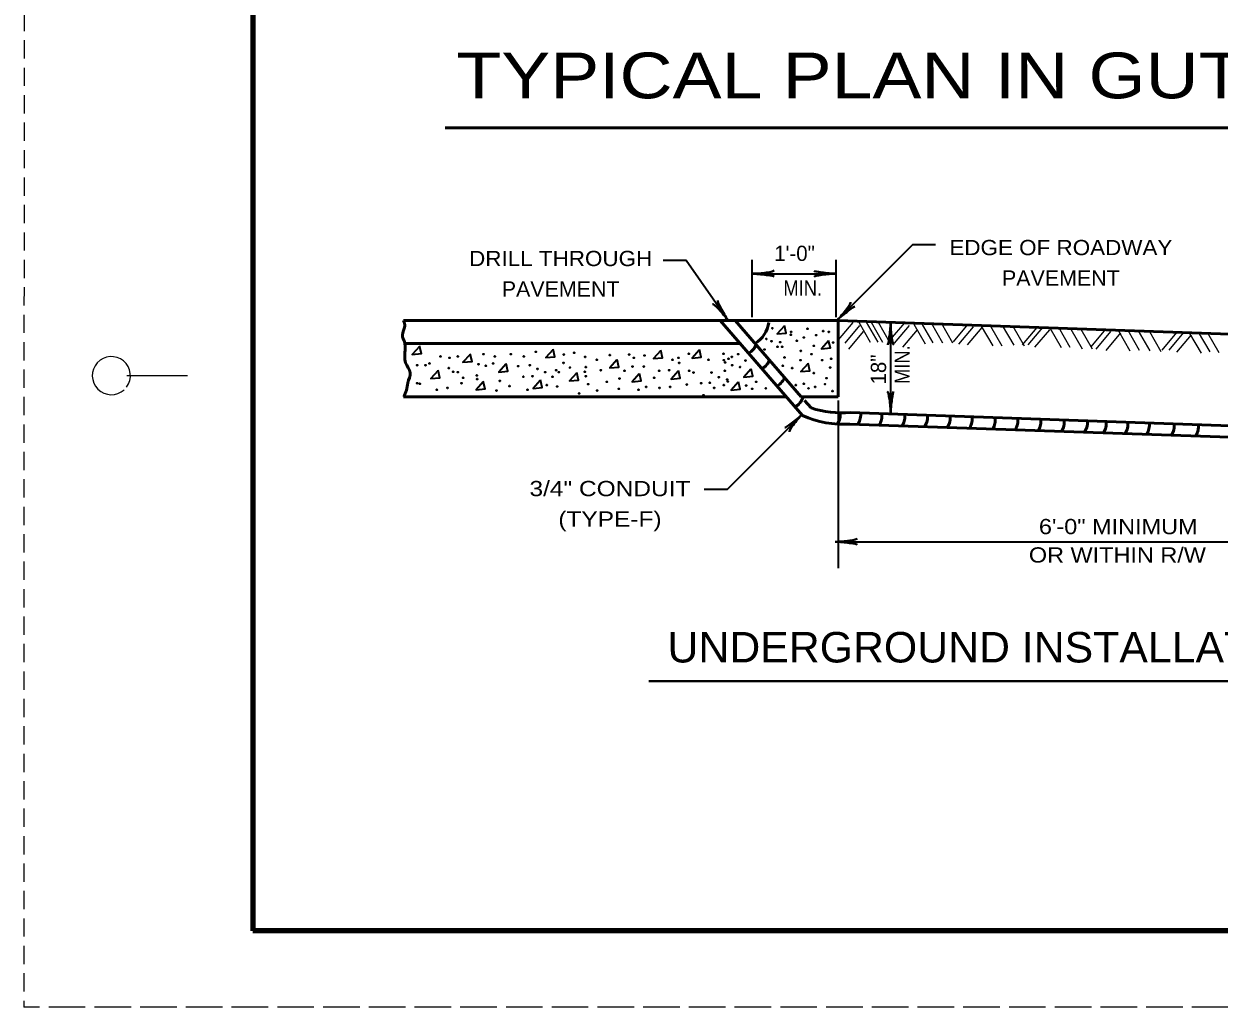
# Model space of a CAD drawing. Extents: x -58 to 622, y -372 to 68.
# Drawn here: x -58.5 to 98.3, y -372 to -243.1 of the extents above; entities that cross this region are included whole.
import ezdxf
from ezdxf.enums import TextEntityAlignment as Align

# ---------------------------------------------------------------- set-up
doc = ezdxf.new("R2010")
doc.units = 0
doc.header["$LTSCALE"] = 0.8
doc.linetypes.add('LONG_DASHED', pattern=[7.5, 6, -1.5])
doc.linetypes.add('MEDIUM_DASHED', pattern=[4.5, 3, -1.5])
doc.layers.add('1', color=7, linetype='Continuous', lineweight=35)
doc.layers.add('61', color=7, linetype='Continuous', lineweight=35)

msp = doc.modelspace()

# ---------------------------------------------------------------- linework, layer by layer
at = {"layer": '1', "linetype": 'MEDIUM_DASHED', "lineweight": 13}
msp.add_line((-58.4297, 67.9933), (-58.4898, -372.0467), dxfattribs=at)
at = {"layer": '1', "lineweight": 53}
for p, q in [((-3.2295, -256.7077), (194.5145, -256.7077)), ((32.8492, -281.9895), (43.6675, -294.4345)), ((34.8368, -281.9895), (43.5093, -291.966)), ((48.3367, -281.9895), (123.3002, -284.6073)), ((-8.6632, -284.9895), (35.4571, -284.9895)), ((41.4103, -291.9895), (-8.6632, -291.9895)), ((48.3367, -291.9895), (43.5063, -291.9895)), ((43.9508, -292.4741), (44.7996, -293.4504)), ((49.9544, -294.0532), (122.8722, -296.5997)), ((49.9021, -295.5523), (122.8199, -298.0987))]:
    msp.add_line(p, q, dxfattribs=at)
at = {"layer": '1'}
for p, q in [((37.076, -281.52), (37.076, -274.02)), ((48.076, -281.5199), (48.076, -274.0199)), ((37.076, -275.8309), (48.076, -275.8309)), ((55.2352, -282.3041), (55.2352, -294.1794)), ((48.3342, -292.4785), (48.3342, -314.4785)), ((47.9859, -310.9966), (123.3332, -310.9966))]:
    msp.add_line(p, q, dxfattribs=at)
at = {"layer": '1', "lineweight": 25}
for p, q in [((50.2675, -282.2197), (48.3392, -284.518)), ((51.0682, -282.2067), (52.5682, -284.8048)), ((52.0416, -282.2067), (53.5416, -284.8048)), ((52.6904, -282.2067), (54.1904, -284.8048)), ((53.5826, -282.2067), (55.0826, -284.8048)), ((57.0807, -282.2197), (55.1523, -284.518)), ((51.1597, -282.6252), (49.2313, -284.9235)), ((51.6463, -283.4362), (49.718, -285.7346)), ((57.6484, -282.6252), (55.7201, -284.9235)), ((58.7028, -283.1929), (56.7745, -285.4912)), ((58.2869, -282.45), (59.7869, -285.0481)), ((59.2602, -282.2878), (60.7602, -284.8858)), ((60.558, -282.2878), (62.058, -284.8858)), ((61.8558, -282.2878), (63.3558, -284.8858)), ((65.3537, -282.463), (63.4254, -284.7613)), ((66.0837, -282.7874), (64.1554, -285.0858)), ((67.2193, -282.8685), (65.2909, -285.1668)), ((67.1278, -282.6933), (68.6278, -285.2914)), ((68.3445, -282.6933), (69.8445, -285.2914)), ((69.8856, -282.6122), (71.3856, -285.2102)), ((71.2644, -282.6933), (72.7644, -285.2914)), ((74.438, -282.8685), (72.5097, -285.1668)), ((75.168, -282.8685), (73.2397, -285.1668)), ((76.0602, -283.1929), (74.1318, -285.4912)), ((76.1309, -282.9366), (77.6309, -285.5347)), ((77.2665, -282.8555), (78.7665, -285.4536)), ((78.8887, -283.0988), (80.3887, -285.6969)), ((80.1864, -283.0988), (81.6864, -285.6969)), ((83.4411, -283.1118), (81.5127, -285.4102)), ((84.09, -283.4362), (82.1617, -285.7346)), ((85.3877, -283.5985), (83.4594, -285.8968)), ((85.1341, -283.3422), (86.6341, -285.9402)), ((86.3507, -283.2611), (87.8507, -285.8592)), ((87.7295, -283.3422), (89.2295, -285.9402)), ((89.1895, -283.4232), (90.6895, -286.0213)), ((92.7281, -283.5579), (90.7998, -285.8562)), ((93.6608, -283.5579), (91.7325, -285.8562)), ((94.6747, -283.8418), (92.7463, -286.1402)), ((94.4616, -283.6666), (95.9616, -286.2647)), ((95.5971, -283.5044), (97.0971, -286.1025)), ((96.8137, -283.5855), (98.3137, -286.1836))]:
    msp.add_line(p, q, dxfattribs=at)
at = {"layer": '1', "lineweight": 40}
msp.add_line((23.5023, -329.2931), (116.8997, -329.2931), dxfattribs=at)
at = {"layer": '1'}
for points in [[(48.2287, -281.9152), (58.1283, -272.0157), (61.1283, -272.0157)], [(33.8785, -281.9368), (28.391, -274.0997), (25.391, -274.0997)], [(41.2724, -282.6997), (40.3511, -283.7362), (41.5411, -283.621), (41.3107, -282.6229)], [(-6.6018, -285.3831), (-7.5231, -286.4196), (-6.3331, -286.3044), (-6.5634, -285.3063)], [(47.0661, -284.6513), (46.1448, -285.6877), (47.3347, -285.5726), (47.1044, -284.5745)], [(0.0457, -286.4198), (-0.8756, -287.4563), (0.3144, -287.3412), (0.0841, -286.3431)], [(10.9013, -285.81), (9.98, -286.8465), (11.17, -286.7313), (10.9397, -285.7332)], [(25.0501, -285.9319), (24.1288, -286.9684), (25.3187, -286.8533), (25.0884, -285.8552)], [(30.1119, -285.871), (29.1906, -286.9075), (30.3806, -286.7923), (30.1502, -285.7942)], [(-4.1623, -288.5543), (-5.0836, -289.5908), (-3.8936, -289.4757), (-4.1239, -288.4776)], [(4.7417, -287.7006), (3.8203, -288.7371), (5.0103, -288.6219), (4.78, -287.6238)], [(19.3174, -287.1517), (18.3961, -288.1882), (19.5861, -288.073), (19.3558, -287.0749)], [(27.3676, -288.6153), (26.4462, -289.6518), (27.6363, -289.5367), (27.4059, -288.5386)], [(36.8814, -288.3714), (35.9601, -289.4079), (37.1501, -289.2928), (36.9198, -288.2947)], [(44.3827, -287.6396), (43.4613, -288.6761), (44.6513, -288.5609), (44.421, -287.5628)], [(1.7533, -290.018), (0.832, -291.0545), (2.022, -290.9393), (1.7917, -289.9412)], [(9.2547, -289.8351), (8.3333, -290.8716), (9.5233, -290.7564), (9.293, -289.7583)], [(14.0116, -288.8592), (13.0902, -289.8957), (14.2802, -289.7806), (14.0499, -288.7825)], [(22.2447, -288.9812), (21.3234, -290.0177), (22.5134, -289.9026), (22.2831, -288.9045)], [(35.2347, -290.079), (34.3134, -291.1155), (35.5034, -291.0003), (35.2731, -290.0023)], [(43.6774, -294.2512), (33.7779, -304.1508), (30.7779, -304.1508)]]:
    msp.add_lwpolyline(points, dxfattribs=at)
at = {"layer": '1', "lineweight": 53}
msp.add_lwpolyline([(-8.6632, -281.9895), (48.3367, -281.9895), (48.3367, -291.9895)], dxfattribs=at)
at = {"layer": '1'}
for centre in [(39.7142, -282.9907), (42.1388, -283.8394), (42.1995, -283.4757), (44.321, -283.0513), (45.4727, -283.9), (46.382, -283.3544), (47.1093, -283.4757), (38.9262, -284.3849), (39.593, -284.688), (40.381, -285.4154), (40.7447, -284.8092), (40.9872, -285.4154), (42.9268, -284.6274), (43.8361, -284.2031), (45.1697, -285.2942), (47.7155, -284.8698), (-3.8079, -286.6883), (-2.6562, -286.8702), (-1.5651, -286.6883), (1.8294, -286.3852), (3.2842, -286.6883), (5.4057, -286.3852), (7.1029, -286.6883), (8.679, -286.0822), (12.3765, -286.4458), (13.7101, -286.2034), (15.1648, -286.7489), (18.3775, -286.5065), (20.9233, -286.4458), (21.5295, -286.8702), (22.9237, -286.5671), (27.4093, -286.8702), (28.7427, -286.3246), (33.289, -286.3246), (33.9558, -286.9914), (34.3801, -286.7489), (35.2287, -286.3852), (38.6837, -285.7791), (41.2903, -286.8096), (43.4724, -285.9609), (44.8666, -286.3852), (47.4124, -286.9914), (-6.8992, -287.84), (-5.8082, -287.84), (-5.2627, -287.5976), (-2.7168, -288.2038), (1.1626, -287.7188), (2.1325, -287.9007), (3.1023, -287.5976), (6.3756, -287.9613), (7.891, -287.84), (8.9214, -288.3249), (11.3461, -288.5068), (12.3159, -287.5369), (13.1645, -288.1431), (15.2255, -288.0825), (16.6803, -287.1127), (17.2257, -288.5068), (20.3172, -288.5674), (21.3477, -288.0218), (22.8631, -288.0218), (24.8633, -288.5674), (26.1969, -288.5068), (26.6212, -287.1127), (27.4698, -287.5369), (28.8034, -288.5674), (31.3492, -287.1127), (33.3496, -287.1732), (33.4708, -288.5674), (33.5314, -287.4763), (34.4407, -287.84), (35.4712, -288.0825), (36.1985, -287.2338), (41.1084, -287.9007), (42.3207, -288.2038), (43.4117, -287.1732), (46.2608, -287.1732), (47.2912, -288.1431), (-2.1713, -288.6887), (-1.5651, -288.7493), (-0.8377, -289.4767), (0.9202, -289.1736), (0.9808, -289.6585), (3.9509, -289.9009), (7.0423, -289.3554), (8.2547, -289.2948), (9.8912, -288.7493), (10.8612, -289.3554), (11.7097, -288.7493), (15.1042, -288.6887), (15.2255, -289.2948), (18.0137, -290.0222), (19.6504, -289.5978), (24.1966, -289.4767), (29.3489, -288.8098), (31.5311, -290.1434), (31.7129, -288.8098), (32.6828, -289.416), (33.7739, -289.7191), (33.8951, -289.9616), (37.5927, -290.0222), (39.1081, -289.1736), (45.1697, -288.8705), (46.8062, -289.5372), (-6.8992, -290.204), (-6.5356, -290.2647), (-4.2928, -291.0527), (-2.8987, -290.8102), (-1.0802, -290.204), (3.5267, -291.1739), (5.2238, -290.5677), (7.5879, -291.0527), (10.1337, -290.4465), (11.4672, -290.6283), (14.3768, -291.5376), (15.5286, -290.3252), (16.7408, -291.1739), (19.5898, -290.9314), (22.1357, -291.0527), (23.1662, -290.6889), (24.924, -290.8102), (26.3182, -290.6889), (28.5003, -290.3859), (30.3794, -290.204), (32.0767, -290.8102), (33.3496, -290.4465), (36.2592, -290.5071), (37.0472, -290.9314), (38.8656, -290.8708), (42.8057, -290.4465), (43.8361, -290.2647), (44.4423, -290.8708), (45.3515, -290.6889), (46.6244, -290.3252), (47.5942, -291.2345), (30.6825, -291.78)]:
    msp.add_circle(centre, 0.0607, dxfattribs=at)
at = {"layer": '1', "lineweight": 53}
for centre, radius, start, end in [((35.4988, -281.7617), 3.7689, 301.08152, 353.13064), ((35.5578, -284.3752), 2.1707, 299.00343, 339.84739), ((37.3543, -286.3513), 2.1707, 299.00343, 339.84739), ((39.3305, -288.6269), 2.1707, 299.00343, 339.84739), ((41.6659, -291.3816), 2.1707, 299.00343, 339.84739), ((48.9991, -282.6433), 12.9405, 245.66897, 274.00127), ((48.9237, -280.526), 13.5665, 252.30241, 274.35724), ((46.4423, -294.3473), 2.1707, 327.00343, 7.84739), ((49.1371, -294.3473), 2.1707, 327.00343, 7.84739), ((51.9217, -294.4969), 2.1707, 327.00343, 7.84739), ((54.9458, -294.5269), 2.1707, 327.00343, 7.84739), ((57.9101, -294.6467), 2.1707, 327.00343, 7.84739), ((60.8743, -294.7664), 2.1707, 327.00343, 7.84739), ((63.7788, -294.8563), 2.1707, 327.00343, 7.84739), ((66.8028, -295.006), 2.1707, 327.00343, 7.84739), ((69.7671, -295.0959), 2.1707, 327.00343, 7.84739), ((72.7913, -295.1857), 2.1707, 327.00343, 7.84739), ((75.8453, -295.3354), 2.1707, 327.00343, 7.84739), ((78.8994, -295.3354), 2.1707, 327.00343, 7.84739), ((81.3547, -295.515), 2.1707, 327.00343, 7.84739), ((84.1992, -295.6049), 2.1707, 327.00343, 7.84739), ((87.0137, -295.6947), 2.1707, 327.00343, 7.84739), ((90.2773, -295.8144), 2.1707, 327.00343, 7.84739), ((93.4512, -295.9342), 2.1707, 327.00343, 7.84739)]:
    msp.add_arc(centre, radius, start, end, dxfattribs=at)
at = {"layer": '1', "lineweight": 40}
for centre, major_axis, ratio, start_param, end_param in [((38.1965, -276.0425), (1.7565, -0.1757), 0.07063, 6.28230741, 8.55970261), ((38.1965, -276.0425), (1.7565, -0.1757), 0.07063, 6.28230741, 8.55970261), ((38.1672, -275.5546), (-1.7857, -0.1562), 0.122415, 0.89635335, 3.14159265), ((38.1672, -275.5546), (-1.7857, -0.1562), 0.122415, 0.89635335, 3.14159265), ((46.9848, -276.1072), (1.7857, 0.1562), 0.122415, 0.89635335, 3.14159265), ((46.9848, -276.1072), (1.7857, 0.1562), 0.122415, 0.89635335, 3.14159265), ((46.9555, -275.6193), (1.7565, -0.1757), 0.07063, 3.14071475, 5.41810995), ((46.9555, -275.6193), (1.7565, -0.1757), 0.07063, 3.14071475, 5.41810995), ((33.0263, -281.2014), (1.1521, -1.3732), 0.122415, 0.89635335, 3.14159265), ((33.4091, -280.8975), (-0.8636, 1.5396), 0.07063, 6.28230741, 8.55970261), ((48.805, -280.9482), (-1.1523, -1.3731), 0.122415, 0.89635335, 3.14159265), ((48.805, -280.9482), (-1.1523, -1.3731), 0.122415, 0.89635335, 3.14159265), ((49.1707, -281.2725), (1.3662, 1.1178), 0.07063, 6.28230741, 8.55970261), ((49.1707, -281.2725), (1.3662, 1.1178), 0.07063, 6.28230741, 8.55970261), ((55.0236, -283.4246), (-0.1757, -1.7565), 0.07063, 6.28230741, 8.55970261), ((55.0236, -283.4246), (-0.1757, -1.7565), 0.07063, 6.28230741, 8.55970261), ((55.5115, -283.3953), (-0.1562, 1.7857), 0.122415, 0.89635335, 3.14159265), ((55.5115, -283.3953), (-0.1562, 1.7857), 0.122415, 0.89635335, 3.14159265), ((54.9589, -293.0882), (0.1562, -1.7857), 0.122415, 0.89635335, 3.14159265), ((54.9589, -293.0882), (0.1562, -1.7857), 0.122415, 0.89635335, 3.14159265), ((55.4468, -293.0589), (0.1757, 1.7565), 0.07063, 6.28230741, 8.55970261), ((55.4468, -293.0589), (0.1757, 1.7565), 0.07063, 6.28230741, 8.55970261), ((42.7355, -294.8939), (1.3662, 1.1178), 0.07063, 3.14071475, 5.41810995), ((43.1012, -295.2182), (1.1523, 1.3731), 0.122415, 0.89635335, 3.14159265), ((49.1064, -311.2082), (1.7565, -0.1757), 0.07063, 6.28230741, 8.55970261), ((49.0771, -310.7203), (-1.7857, -0.1562), 0.122415, 0.89635335, 3.14159265)]:
    msp.add_ellipse(centre, major_axis=major_axis, ratio=ratio, start_param=start_param, end_param=end_param, dxfattribs=at)
at = {"layer": '1', "lineweight": 53}
msp.add_spline([(-8.6632, -281.9895), (-8.5245, -282.726), (-8.8239, -283.8637), (-8.5245, -284.8818), (-8.4646, -285.6602), (-8.4047, -287.5167), (-7.8059, -288.8341), (-8.1053, -290.1515), (-8.285, -291.1097), (-8.6632, -291.9895)], degree=3, dxfattribs=at)
at = {"layer": '61', "lineweight": 13}
msp.add_line((-44.9898, -289.2067), (-37.0097, -289.2067), dxfattribs=at)
at = {"layer": '61', "lineweight": 158}
msp.add_line((610.6302, -362.0467), (-28.4297, -362.0267), dxfattribs=at)
at = {"layer": '61', "linetype": 'LONG_DASHED', "lineweight": 13}
msp.add_line((621.5702, -372.0267), (-58.4898, -372.0467), dxfattribs=at)
at = {"layer": '61', "lineweight": 158}
msp.add_lwpolyline([(610.6102, 57.9933), (-28.4297, 57.9933), (-28.4297, -362.0267)], dxfattribs=at)
at = {"layer": '61', "lineweight": 13}
msp.add_arc((-47.012, -289.2054), 2.5, 323.13009, 312.31439, dxfattribs=at)

# ---------------------------------------------------------------- texts
at = {"layer": '1'}
for s, height, width, p in [('TYPICAL PLAN IN GUTTER AND SIDEWALK', 6, 1.2, (-1.7292, -252.8244)), ('MIN.', 2, 0.9, (41.1625, -278.7109)), ('6\'-0" MINIMUM', 2, 1.15, (74.6907, -310.005)), ('OR WITHIN R/W', 2, 1.15, (73.3732, -313.7283)), ('UNDERGROUND INSTALLATION', 4, 1.05, (25.9601, -326.8357))]:
    msp.add_text(s, height=height, dxfattribs=dict(at, width=width)).set_placement(p)
for s, width, p in [('DRILL THROUGH', 1.1, (11.9392, -274.8365)), ('EDGE OF ROADWAY', 1.1, (77.572, -273.3993)), ('PAVEMENT', 1.05, (77.572, -277.3993)), ('PAVEMENT', 1.05, (11.9392, -278.8365)), ('3/4" CONDUIT', 1.2, (18.4067, -305.018)), ('(TYPE-F)', 1.2, (18.4067, -309.018))]:
    msp.add_text(s, height=2, dxfattribs=dict(at, width=width)).set_placement(p, align=Align.CENTER)
msp.add_text('1\'-0"', height=2, dxfattribs=at).set_placement((39.9648, -274.1597))
msp.add_text('18"', height=2, rotation=90, dxfattribs=at).set_placement((54.6366, -290.3577))
at = {"layer": '1', "width": 0.9}
msp.add_text('MIN.', height=2, rotation=90, dxfattribs=at).set_placement((57.7504, -290.2978))

doc.saveas('drawing.dxf')
